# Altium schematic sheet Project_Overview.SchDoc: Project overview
size A4; Date: Not used; ApprovedBy: Not used; CheckedBy: Not used; Author: Not used; CompanyName: STMicroelectronics; DrawnBy: Not used; Engineer: Not used; Organization: Not used; Address1: Not used; Address2: Not used; Address3: Not used; Address4: Not used; DocumentNumber: 1; Revision: Not used; SheetNumber: 1; SheetTotal: 12
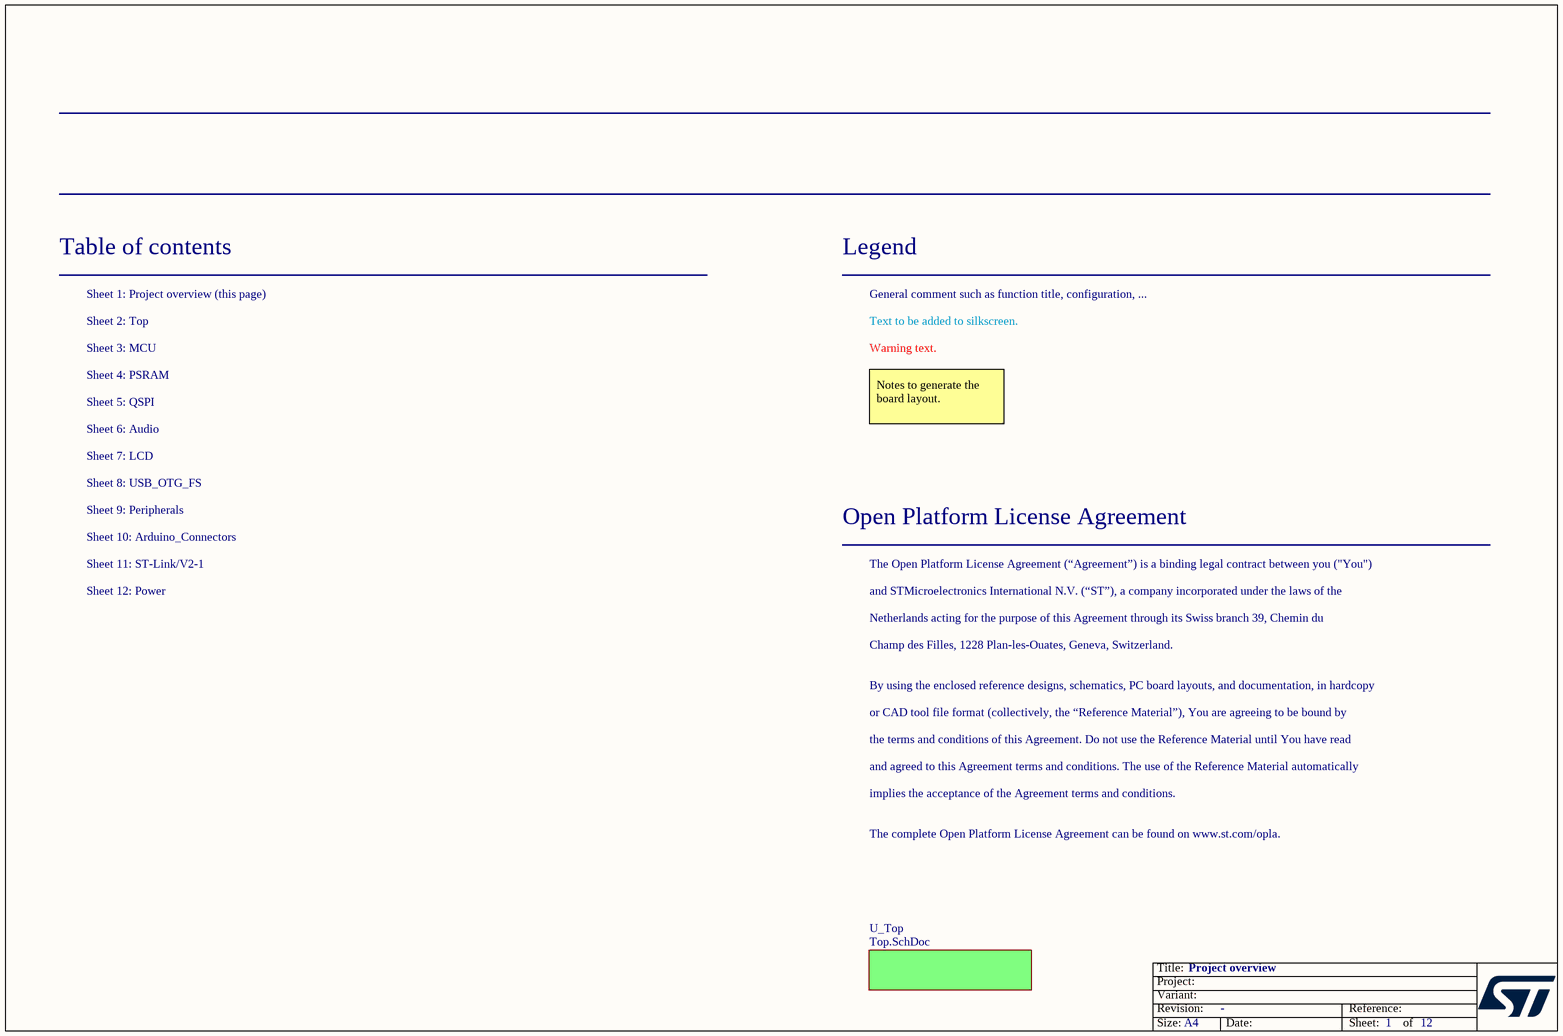
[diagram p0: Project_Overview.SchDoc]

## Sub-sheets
U_Top = Top.SchDoc: no entries

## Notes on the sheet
- Table of contents
- Sheet 1: Project overview (this page)
- Legend
- General comment such as function title, configuration, ...
- Sheet 2: Top
- Sheet 3: MCU
- Sheet 4: PSRAM
- Text to be added to silkscreen.
- Warning text.
- Sheet 6: Audio
- Sheet 5: QSPI
- Notes to generate the board layout.
- Sheet 7: LCD
- Sheet 8: USB_OTG_FS
- Sheet 9: Peripherals
- Sheet 11: ST-Link/V2-1
- Sheet 10: Arduino_Connectors
- Open Platform License Agreement
- The Open Platform License Agreement (“Agreement”) is a binding legal contract between you ("You")
- Sheet 12: Power
- and STMicroelectronics International N.V. (“ST”), a company incorporated under the laws of the
- Netherlands acting for the purpose of this Agreement through its Swiss branch 39, Chemin du
- Champ des Filles, 1228 Plan-les-Ouates, Geneva, Switzerland.
- By using the enclosed reference designs, schematics, PC board layouts, and documentation, in hardcopy
- or CAD tool file format (collectively, the “Reference Material”), You are agreeing to be bound by
- the terms and conditions of this Agreement. Do not use the Reference Material until You have read
- and agreed to this Agreement terms and conditions. The use of the Reference Material automatically
- implies the acceptance of the Agreement terms and conditions.
- The complete Open Platform License Agreement can be found on www.st.com/opla.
